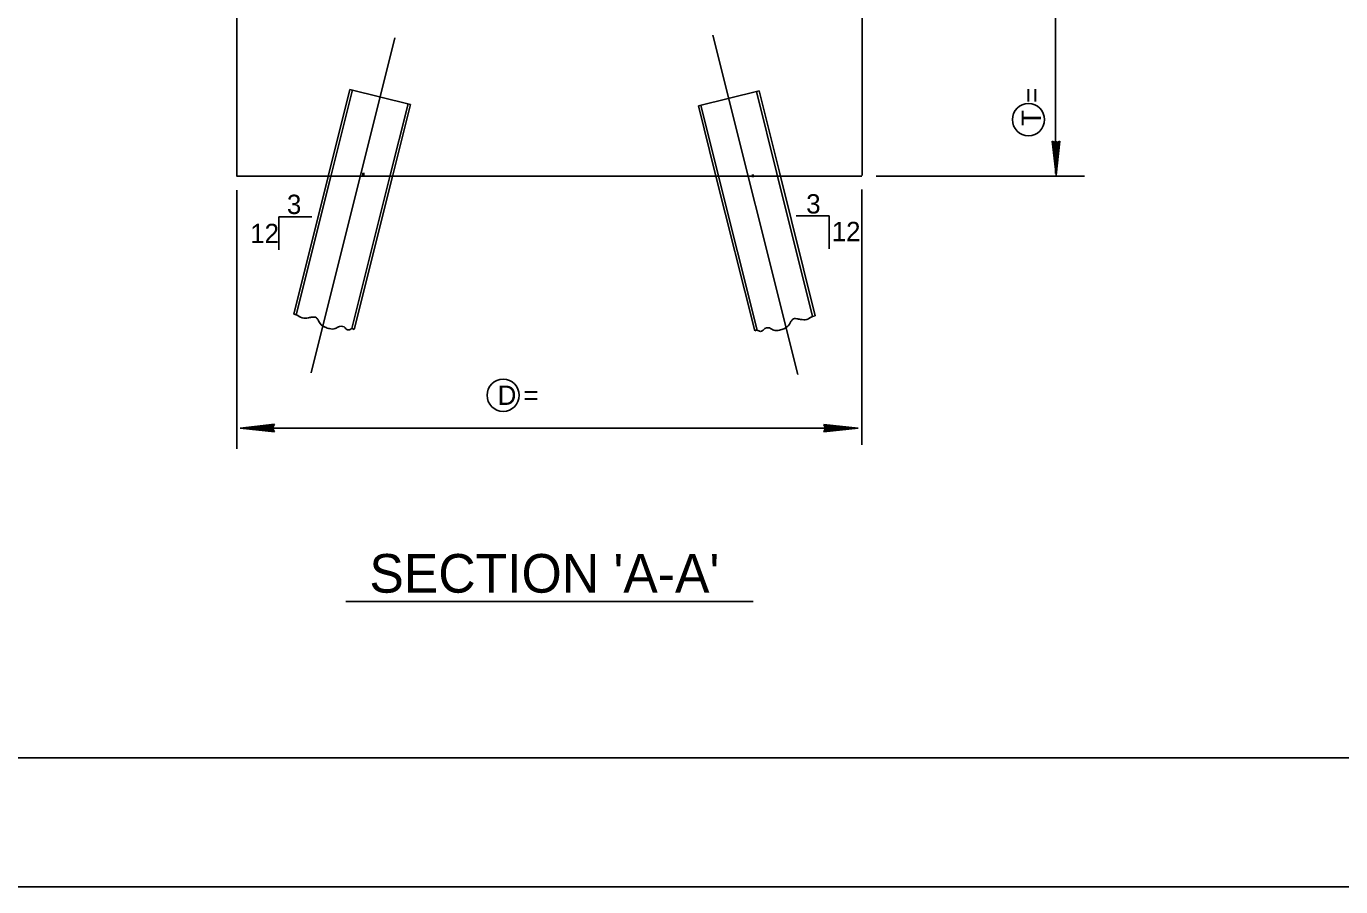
# Model space of a CAD drawing. Extents: x 1.6 to 6.29, y 2.8 to 7.08.
# Drawn here: x 3.813 to 4.663, y 4.675 to 5.231 of the extents above; entities that cross this region are included whole.
import ezdxf

# ---------------------------------------------------------------- set-up
doc = ezdxf.new("R2010")
doc.units = 0
doc.layers.add('Level 1', color=7, linetype='Continuous')
doc.layers.add('Level 5', color=7, linetype='Continuous')

msp = doc.modelspace()

# ---------------------------------------------------------------- linework, layer by layer
at = {"layer": 'Level 1'}
for p, q in [((4.47858, 5.79125), (4.47858, 5.13608)), ((3.94917, 5.28592), (3.94917, 5.13467)), ((4.3535, 5.28533), (4.3535, 5.13483)), ((4.479, 5.135), (4.47658, 5.15708)), ((4.47658, 5.15708), (4.47908, 5.15592)), ((4.47692, 5.15667), (4.47867, 5.14125)), ((4.478, 5.15617), (4.477, 5.15667)), ((4.47717, 5.15667), (4.47883, 5.14125)), ((4.47742, 5.15667), (4.47908, 5.14133)), ((4.47767, 5.15667), (4.47942, 5.14142)), ((4.479, 5.15567), (4.478, 5.15617)), ((4.47933, 5.14458), (4.478, 5.156)), ((4.478, 5.156), (4.47933, 5.1555)), ((4.4785, 5.1505), (4.4785, 5.15592)), ((4.4785, 5.15592), (4.47933, 5.14458)), ((4.47883, 5.15558), (4.4785, 5.1505)), ((4.47892, 5.138), (4.47883, 5.15558)), ((4.479, 5.15708), (4.479, 5.135)), ((4.4815, 5.15708), (4.479, 5.135)), ((4.48075, 5.15667), (4.479, 5.14025)), ((4.48058, 5.15533), (4.479, 5.15567)), ((4.47908, 5.15592), (4.4815, 5.15708)), ((4.48092, 5.15667), (4.47908, 5.14025)), ((4.48108, 5.15667), (4.47933, 5.14017)), ((4.47933, 5.1555), (4.48083, 5.1565)), ((4.48125, 5.15667), (4.47942, 5.14017)), ((4.48117, 5.15667), (4.47942, 5.14017)), ((4.47942, 5.15558), (4.47942, 5.14575)), ((4.47942, 5.14767), (4.47942, 5.15558)), ((4.47942, 5.15558), (4.47975, 5.14925)), ((4.48017, 5.15608), (4.47967, 5.1485)), ((4.4805, 5.156), (4.47967, 5.1555)), ((4.47967, 5.1555), (4.47983, 5.155)), ((4.47975, 5.14925), (4.47975, 5.15592)), ((4.47975, 5.15592), (4.47992, 5.15125)), ((4.47983, 5.155), (4.48058, 5.15533)), ((4.47992, 5.15125), (4.48017, 5.15608)), ((4.48083, 5.1565), (4.4805, 5.156)), ((4.47967, 5.1485), (4.47917, 5.13867)), ((4.47917, 5.14583), (4.47942, 5.14767)), ((4.47942, 5.14575), (4.47917, 5.14583)), ((4.47917, 5.13867), (4.47867, 5.14075)), ((4.47867, 5.14075), (4.47892, 5.138)), ((3.94883, 5.13433), (4.06575, 5.13433)), ((4.06575, 5.13433), (4.35342, 5.13433)), ((4.36267, 5.13433), (4.49733, 5.13433)), ((3.94908, 5.12525), (3.94908, 4.95792)), ((4.35342, 5.12583), (4.35342, 4.96067)), ((3.95133, 4.97142), (3.97342, 4.97392)), ((3.97342, 4.97142), (3.95133, 4.97142)), ((3.97342, 4.969), (3.95133, 4.97142)), ((3.95133, 4.97142), (4.351, 4.97142)), ((3.957, 4.97183), (3.95433, 4.97158)), ((3.95433, 4.97158), (3.97192, 4.97167)), ((3.955, 4.97125), (3.957, 4.97183)), ((3.96483, 4.97083), (3.955, 4.97125)), ((3.97292, 4.96933), (3.9565, 4.97117)), ((3.97292, 4.96942), (3.9565, 4.97117)), ((3.97292, 4.96925), (3.9565, 4.97108)), ((3.973, 4.96975), (3.95658, 4.9715)), ((3.97292, 4.9695), (3.95658, 4.97133)), ((3.97292, 4.9735), (3.95758, 4.97183)), ((3.97292, 4.97333), (3.95758, 4.97167)), ((3.973, 4.97308), (3.95767, 4.97142)), ((3.973, 4.97283), (3.95767, 4.97117)), ((3.96092, 4.97117), (3.97225, 4.97242)), ((3.97217, 4.972), (3.96092, 4.97117)), ((3.96208, 4.971), (3.96208, 4.97125)), ((3.96208, 4.97125), (3.964, 4.97117)), ((3.97192, 4.97117), (3.96208, 4.971)), ((3.964, 4.97117), (3.97192, 4.971)), ((3.97233, 4.97025), (3.96483, 4.97083)), ((3.97192, 4.971), (3.96558, 4.97083)), ((3.96558, 4.97083), (3.97217, 4.97067)), ((3.97192, 4.97167), (3.96675, 4.972)), ((3.96675, 4.972), (3.97217, 4.972)), ((3.97217, 4.97067), (3.9675, 4.9705)), ((3.9675, 4.9705), (3.97233, 4.97025)), ((3.97183, 4.97083), (3.97125, 4.97058)), ((3.97125, 4.97058), (3.97167, 4.96992)), ((3.97167, 4.96992), (3.972, 4.9715)), ((3.97225, 4.97242), (3.97183, 4.97117)), ((3.97183, 4.97117), (3.97275, 4.96967)), ((3.97225, 4.97), (3.97183, 4.97083)), ((3.972, 4.9715), (3.97242, 4.97242)), ((3.97342, 4.97392), (3.97225, 4.97142)), ((3.97225, 4.97142), (3.97342, 4.969)), ((3.97275, 4.96967), (3.97225, 4.97)), ((3.97242, 4.97242), (3.97292, 4.9735)), ((4.32875, 4.97383), (4.351, 4.97142)), ((4.32992, 4.97142), (4.32875, 4.97383)), ((4.32875, 4.97142), (4.351, 4.97142)), ((4.351, 4.97142), (4.32875, 4.96892)), ((4.32875, 4.96892), (4.32992, 4.97142)), ((4.32908, 4.97), (4.34458, 4.97167)), ((4.32917, 4.9735), (4.34575, 4.97167)), ((4.32917, 4.97342), (4.34575, 4.97158)), ((4.32917, 4.97333), (4.34575, 4.9715)), ((4.32917, 4.97308), (4.34575, 4.97125)), ((4.32917, 4.96975), (4.34458, 4.97142)), ((4.32917, 4.9695), (4.34467, 4.97117)), ((4.32925, 4.97358), (4.34575, 4.97175)), ((4.32925, 4.96925), (4.34467, 4.971)), ((4.32967, 4.97042), (4.32925, 4.96933)), ((4.33033, 4.97158), (4.32933, 4.97317)), ((4.32933, 4.97317), (4.32983, 4.97283)), ((4.33008, 4.97133), (4.32967, 4.97042)), ((4.33458, 4.97233), (4.32975, 4.97258)), ((4.32975, 4.97258), (4.33742, 4.972)), ((4.32983, 4.97283), (4.33033, 4.972)), ((4.34125, 4.97158), (4.32983, 4.97042)), ((4.32983, 4.97042), (4.33033, 4.97158)), ((4.33, 4.97217), (4.33458, 4.97233)), ((4.33667, 4.972), (4.33, 4.97217)), ((4.33, 4.97083), (4.34125, 4.97158)), ((4.33542, 4.97083), (4.33, 4.97083)), ((4.33042, 4.97292), (4.33008, 4.97133)), ((4.33025, 4.97183), (4.33667, 4.972)), ((4.33025, 4.97167), (4.34017, 4.97183)), ((4.33825, 4.97167), (4.33025, 4.97183)), ((4.348, 4.97125), (4.33025, 4.97117)), ((4.33025, 4.97117), (4.33542, 4.97083)), ((4.33033, 4.972), (4.33083, 4.97225)), ((4.33083, 4.97225), (4.33042, 4.97292)), ((4.33742, 4.972), (4.34725, 4.97158)), ((4.34008, 4.97158), (4.33825, 4.97167)), ((4.34017, 4.97183), (4.34008, 4.97158)), ((4.34725, 4.97158), (4.34525, 4.971)), ((4.34525, 4.971), (4.348, 4.97125)), ((4.01967, 4.85917), (4.28308, 4.85917)), ((2.55808, 4.758), (6.18475, 4.758)), ((2.55808, 4.758), (5.46475, 4.758)), ((2.39142, 4.67467), (6.26142, 4.67467))]:
    msp.add_line(p, q, dxfattribs=at)
for centre in [(4.46119, 5.17096), (4.12135, 4.99262)]:
    msp.add_circle(centre, 0.01042, dxfattribs=at)
at = {"layer": 'Level 5'}
for p, q in [((4.05133, 5.22383), (3.99725, 5.00717)), ((4.25708, 5.22558), (4.31192, 5.00617)), ((4.02225, 5.19058), (4.00808, 5.13408)), ((4.024, 5.19017), (4.00992, 5.13408)), ((4.02225, 5.19058), (4.0615, 5.18083)), ((4.28692, 5.18958), (4.24767, 5.17983)), ((4.28517, 5.18917), (4.29842, 5.13617)), ((4.28692, 5.18958), (4.30025, 5.13617)), ((4.05983, 5.18125), (4.048, 5.13408)), ((4.0615, 5.18083), (4.04975, 5.13408)), ((4.24767, 5.17983), (4.25858, 5.13617)), ((4.24933, 5.18025), (4.26033, 5.13617)), ((4.25858, 5.13617), (4.28408, 5.03425)), ((4.26033, 5.13617), (4.28575, 5.03475)), ((4.29842, 5.13617), (4.32158, 5.04367)), ((4.30025, 5.13617), (4.32325, 5.04408)), ((4.00808, 5.13408), (3.98592, 5.04508)), ((4.00992, 5.13408), (3.98758, 5.04467)), ((4.048, 5.13408), (4.02342, 5.03575)), ((4.04975, 5.13408), (4.02508, 5.03525)), ((3.9975, 5.10817), (3.97617, 5.10817)), ((3.97617, 5.10817), (3.97617, 5.08683)), ((4.31092, 5.10875), (4.33225, 5.10875)), ((4.33225, 5.10875), (4.33225, 5.08742))]:
    msp.add_line(p, q, dxfattribs=at)
for points in [[(3.98592, 5.04508), (3.98758, 5.04467), (3.99133, 5.04275), (3.9955, 5.04275), (3.99783, 5.04317), (4.00067, 5.04275), (4.00108, 5.04225), (4.00208, 5.04042), (4.003, 5.039), (4.00625, 5.03667), (4.009, 5.03575), (4.01275, 5.03575), (4.0155, 5.03717), (4.01925, 5.03625), (4.02017, 5.03525), (4.0225, 5.03525), (4.02342, 5.03575), (4.02508, 5.03525)], [(4.32325, 5.04408), (4.32158, 5.04367), (4.31783, 5.04175), (4.31367, 5.04175), (4.31133, 5.04217), (4.3085, 5.04175), (4.30808, 5.04125), (4.30708, 5.03942), (4.30617, 5.038), (4.30292, 5.03567), (4.30017, 5.03475), (4.29642, 5.03475), (4.29367, 5.03617), (4.28992, 5.03525), (4.289, 5.03425), (4.28667, 5.03425), (4.28575, 5.03475), (4.28408, 5.03425)]]:
    msp.add_spline(points, degree=3, dxfattribs=at)

# ---------------------------------------------------------------- texts
at = {"layer": 'Level 1'}
msp.add_text("SECTION 'A-A'", height=0.025, dxfattribs=at).set_placement((4.03483, 4.86492))
at = {"layer": 'Level 5'}
msp.add_text('T =      ', height=0.0125, rotation=90, dxfattribs=at).set_placement((4.46925, 5.16692))
for s, p in [('.', (4.02858, 5.13467)), ('.', (4.28058, 5.13367)), ('3', (3.9815, 5.10992)), ('3', (4.31742, 5.11025)), ('12', (3.95775, 5.09108)), ('12', (4.33392, 5.09233)), ('D =      ', (4.11783, 4.98642))]:
    msp.add_text(s, height=0.0125, dxfattribs=at).set_placement(p)

doc.saveas('drawing.dxf')
